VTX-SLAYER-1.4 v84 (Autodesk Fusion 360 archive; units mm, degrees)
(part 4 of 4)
sketch "pressnut3" plane through (0, 0, 7) normal (0, 0, 1) x axis (-1, 0, 0)
  line L1 (-29.8656, 20.8741) -> (-30.0883, 21.2598)
  line L2 (-29.6425, 21.2606) -> (-29.8656, 20.8741)
  line L3 (-29.3373, 20.9286) -> (-29.6331, 21.2615)
  line L4 (-29.1966, 21.352) -> (-29.3373, 20.9286)
  line L5 (-28.8308, 21.0883) -> (-29.1875, 21.3549)
  line L6 (-28.7781, 21.5314) -> (-28.8308, 21.0883)
  line L7 (-28.3667, 21.3467) -> (-28.7698, 21.536)
  line L8 (-28.4044, 21.7913) -> (-28.3667, 21.3467)
  line L9 (-27.9642, 21.6932) -> (-28.3972, 21.7975)
  line L10 (-28.0906, 22.1212) -> (-27.9642, 21.6932)
  line L11 (-27.6397, 22.1137) -> (-28.0848, 22.1287)
  line L12 (-27.8496, 22.5074) -> (-27.6397, 22.1137)
  line L13 (-27.4064, 22.5908) -> (-27.8454, 22.516)
  line L14 (-27.6913, 22.9343) -> (-27.4064, 22.5908)
  line L15 (-27.274, 23.1052) -> (-27.6889, 22.9435)
  line L16 (-27.6222, 23.3843) -> (-27.274, 23.1052)
  line L17 (-27.2478, 23.6357) -> (-27.6217, 23.3938)
  line L18 (-27.6451, 23.8389) -> (-27.2478, 23.6357)
  line L19 (-27.329, 24.1606) -> (-27.6465, 23.8483)
  line L20 (-27.759, 24.2797) -> (-27.329, 24.1606)
  line L21 (-27.5141, 24.6584) -> (-27.7623, 24.2886)
  line L22 (-27.9593, 24.6885) -> (-27.5141, 24.6584)
  line L23 (-27.7957, 25.1088) -> (-27.9644, 24.6966)
  line L24 (-28.2379, 25.0486) -> (-27.7957, 25.1088)
  line L25 (-28.1622, 25.4932) -> (-28.2444, 25.0555)
  line L26 (-28.5832, 25.3453) -> (-28.1622, 25.4932)
  line L27 (-28.5985, 25.796) -> (-28.591, 25.3507)
  line L28 (-28.9811, 25.5664) -> (-28.5985, 25.796)
  line L29 (-29.0869, 26.0048) -> (-28.9899, 25.5702)
  line L30 (-29.4155, 25.7029) -> (-29.0869, 26.0048)
  line L31 (-29.6073, 26.111) -> (-29.4248, 25.7048)
  line L32 (-29.8684, 25.7491) -> (-29.6073, 26.111)
  line L33 (-30.1384, 26.1103) -> (-29.8779, 25.7491)
  line L34 (-30.3213, 25.7032) -> (-30.1384, 26.1103)
  line L35 (-30.6585, 26.0026) -> (-30.3306, 25.7013)
  line L36 (-30.7557, 25.5671) -> (-30.6585, 26.0026)
  line L37 (-31.1463, 25.7925) -> (-30.7645, 25.5634)
  line L38 (-31.1539, 25.3463) -> (-31.1463, 25.7925)
  line L39 (-31.5819, 25.4885) -> (-31.1617, 25.3409)
  line L40 (-31.4994, 25.0499) -> (-31.5819, 25.4885)
  line L41 (-31.9473, 25.103) -> (-31.506, 25.043)
  line L42 (-31.7782, 24.69) -> (-31.9473, 25.103)
  line L43 (-32.2276, 24.6519) -> (-31.7833, 24.682)
  line L44 (-31.9789, 24.2814) -> (-32.2276, 24.6519)
  line L45 (-32.4114, 24.1536) -> (-31.9822, 24.2725)
  line L46 (-32.0932, 23.8407) -> (-32.4114, 24.1536)
  line L47 (-32.4911, 23.6285) -> (-32.0946, 23.8313)
  line L48 (-32.1164, 23.3861) -> (-32.4911, 23.6285)
  line L49 (-32.4634, 23.098) -> (-32.1159, 23.3766)
  line L50 (-32.0477, 22.936) -> (-32.4634, 23.098)
  line L51 (-32.3296, 22.5841) -> (-32.0453, 22.9268)
  line L52 (-31.8897, 22.509) -> (-32.3296, 22.5841)
  line L53 (-32.095, 22.1075) -> (-31.8855, 22.5005)
  line L54 (-31.6491, 22.1226) -> (-32.095, 22.1075)
  line L55 (-31.7694, 21.688) -> (-31.6432, 22.1151)
  line L56 (-31.3355, 21.7925) -> (-31.7694, 21.688)
  line L57 (-31.3659, 21.3425) -> (-31.3283, 21.7863)
  line L58 (-30.962, 21.5323) -> (-31.3659, 21.3425)
  line L59 (-30.9011, 21.0854) -> (-30.9537, 21.5277)
  line L60 (-30.5437, 21.3526) -> (-30.9011, 21.0854)
  line L61 (-30.3941, 20.9271) -> (-30.5346, 21.3497)
  line L62 (-30.0978, 21.2608) -> (-30.3941, 20.9271)
  circle C1 centre (-29.8693, 23.4991) radius 1.55
  arc A1 centre (-29.8693, 23.4991) radius 2.25 clockwise from (-30.0883, 21.2598) to (-30.0978, 21.2608)
  arc A2 centre (-29.8693, 23.4991) radius 2.25 clockwise from (-29.6331, 21.2615) to (-29.6425, 21.2606)
  arc A3 centre (-29.8693, 23.4991) radius 2.25 clockwise from (-29.1875, 21.3549) to (-29.1966, 21.352)
  arc A4 centre (-29.8693, 23.4991) radius 2.25 clockwise from (-28.7698, 21.536) to (-28.7781, 21.5314)
  arc A5 centre (-29.8693, 23.4991) radius 2.25 clockwise from (-28.3972, 21.7975) to (-28.4044, 21.7913)
  arc A6 centre (-29.8693, 23.4991) radius 2.25 clockwise from (-28.0848, 22.1287) to (-28.0906, 22.1212)
  arc A7 centre (-29.8693, 23.4991) radius 2.25 clockwise from (-27.8454, 22.516) to (-27.8496, 22.5074)
  arc A8 centre (-29.8693, 23.4991) radius 2.25 clockwise from (-27.6889, 22.9435) to (-27.6913, 22.9343)
  arc A9 centre (-29.8693, 23.4991) radius 2.25 clockwise from (-27.6217, 23.3938) to (-27.6222, 23.3843)
  arc A10 centre (-29.8693, 23.4991) radius 2.25 clockwise from (-27.6465, 23.8483) to (-27.6451, 23.8389)
  arc A11 centre (-29.8693, 23.4991) radius 2.25 clockwise from (-27.7623, 24.2886) to (-27.759, 24.2797)
  arc A12 centre (-29.8693, 23.4991) radius 2.25 clockwise from (-27.9644, 24.6966) to (-27.9593, 24.6885)
  arc A13 centre (-29.8693, 23.4991) radius 2.25 clockwise from (-28.2444, 25.0555) to (-28.2379, 25.0486)
  arc A14 centre (-29.8693, 23.4991) radius 2.25 clockwise from (-28.591, 25.3507) to (-28.5832, 25.3453)
  arc A15 centre (-29.8693, 23.4991) radius 2.25 clockwise from (-28.9899, 25.5702) to (-28.9811, 25.5664)
  arc A16 centre (-29.8693, 23.4991) radius 2.25 clockwise from (-29.4248, 25.7048) to (-29.4155, 25.7029)
  arc A17 centre (-29.8693, 23.4991) radius 2.25 clockwise from (-29.8779, 25.7491) to (-29.8684, 25.7491)
  arc A18 centre (-29.8693, 23.4991) radius 2.25 clockwise from (-30.3306, 25.7013) to (-30.3213, 25.7032)
  arc A19 centre (-29.8693, 23.4991) radius 2.25 clockwise from (-30.7645, 25.5634) to (-30.7557, 25.5671)
  arc A20 centre (-29.8693, 23.4991) radius 2.25 clockwise from (-31.1617, 25.3409) to (-31.1539, 25.3463)
  arc A21 centre (-29.8693, 23.4991) radius 2.25 clockwise from (-31.506, 25.043) to (-31.4994, 25.0499)
  arc A22 centre (-29.8693, 23.4991) radius 2.25 clockwise from (-31.7833, 24.682) to (-31.7782, 24.69)
  arc A23 centre (-29.8693, 23.4991) radius 2.25 clockwise from (-31.9822, 24.2725) to (-31.9789, 24.2814)
  arc A24 centre (-29.8693, 23.4991) radius 2.25 clockwise from (-32.0946, 23.8313) to (-32.0932, 23.8407)
  arc A25 centre (-29.8693, 23.4991) radius 2.25 clockwise from (-32.1159, 23.3766) to (-32.1164, 23.3861)
  arc A26 centre (-29.8693, 23.4991) radius 2.25 clockwise from (-32.0453, 22.9268) to (-32.0477, 22.936)
  arc A27 centre (-29.8693, 23.4991) radius 2.25 clockwise from (-31.8855, 22.5005) to (-31.8897, 22.509)
  arc A28 centre (-29.8693, 23.4991) radius 2.25 clockwise from (-31.6432, 22.1151) to (-31.6491, 22.1226)
  arc A29 centre (-29.8693, 23.4991) radius 2.25 clockwise from (-31.3283, 21.7863) to (-31.3355, 21.7925)
  arc A30 centre (-29.8693, 23.4991) radius 2.25 clockwise from (-30.9537, 21.5277) to (-30.962, 21.5323)
  arc A31 centre (-29.8693, 23.4991) radius 2.25 clockwise from (-30.5346, 21.3497) to (-30.5437, 21.3526)
  circle C2 centre (-29.8693, 23.4991) radius 3.05
  concentric C1 C2
  dimension "d1051" diameter C2 = 6.1
extrude "Extrude126" add sketch "pressnut3" along normal blind 1.3
copy_paste_bodies "CopyPasteBodies11"
move "Move22"
copy_paste_bodies "CopyPasteBodies12"
move "Move23"
component_from_bodies "Body->Comp25"
component_from_bodies "Body->Comp26"
component_from_bodies "Body->Comp27"
component_from_bodies "Body->Comp28"
component_from_bodies "Body->Comp29"
component_from_bodies "Body->Comp30"
joint "Assemble33" alignAngle 0 alignOffsetX 0 alignOffsetY 0 alignOffsetZ 0
joint "Assemble34" alignAngle 0 alignOffsetX 0 alignOffsetY 0 alignOffsetZ 0
component_insert "Component Insert30"
joint "Assemble35" alignAngle 0 alignOffsetX 0 alignOffsetY 0 alignOffsetZ 0
base_feature "Base Feature1" bodies "arm-fr"
mirror_component "MirrorComponent1"
derived_instance "DerivedInstance1"
mirror_component "MirrorComponent2"
derived_instance "DerivedInstance2"
derived_instance "DerivedInstance3"
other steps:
derived_base_feature "Derived Base Feature1" bodies "arm-fr (1)"
derived_base_feature "Derived Base Feature1" bodies "arm-fr"
base_feature "Base Feature1" bodies "turtleFin"
base_feature "Base Feature1" bodies "vtx-antenna-mount"
derived_base_feature "Derived Base Feature1" bodies "arm-fr (1)", "arm-fr"
base_feature "Base Feature1" bodies "arm-fr"
base_feature "Base Feature1" bodies "arm-rr"
base_feature "Base Feature1" bodies "arm-fl (1)"
base_feature "Base Feature1" bodies "arm-rl"
base_feature "Base Feature1" bodies "m-center"
base_feature "Base Feature1" bodies "m-bottom"
base_feature "Base Feature1" bodies "m-top"
base_feature "Base Feature1" bodies "top (1)"
base_feature "Base Feature1" bodies "cam-mount"
base_feature "Base Feature1" bodies "standoff1 (1)"
base_feature "Base Feature1" bodies "standoff2 (1)"
base_feature "Base Feature1" bodies "standoff1"
base_feature "Base Feature1" bodies "standoff2"
base_feature "Base Feature1" bodies "pressnut1"
base_feature "Base Feature1" bodies "pressnut2"
base_feature "Base Feature1" bodies "pressnut4"
base_feature "Base Feature1" bodies "pressnut5"
base_feature "Base Feature9" bodies "m-bottom", "m-top"
base_feature "Base Feature13" bodies "standoff1", "standoff2", "standoff1 (1)", "standoff2 (1)"
base_feature "Base Feature11" bodies "pressnut", "pressnut2"
base_feature "Base Feature12" bodies "pressnut (1)", "pressnut (1) (1)", "pressnut4", "pressnut5"
joint_origin "JointOrigin14"
joint_origin "JointOrigin15"
joint_origin "JointOrigin16"
joint_origin "JointOrigin17"
joint_origin "JointOrigin18"
joint_origin "JointOrigin19"
joint_origin "JointOrigin20"
joint_origin "JointOrigin21"
joint_origin "JointOrigin22"
joint_origin "JointOrigin23"
joint_origin "JointOrigin24"
joint_origin "JointOrigin25"
joint_origin "JointOrigin26"
joint_origin "JointOrigin27"
joint_origin "JointOrigin28"
joint_origin "JointOrigin29"
joint_origin "JointOrigin30"
create_component "CreateComponent11"
remove_body "RemoveBody11"
create_component "CreateComponent12"
remove_body "RemoveBody12"
create_component "CreateComponent13"
create_component "CreateComponent14"
remove_body "RemoveBody14"
create_component "CreateComponent15"
remove_body "RemoveBody15"
create_component "CreateComponent16"
remove_body "RemoveBody16"
create_component "CreateComponent17"
remove_body "RemoveBody17"
create_component "CreateComponent18"
create_component "CreateComponent19"
remove_body "RemoveBody19"
create_component "CreateComponent21"
create_component "CreateComponent22"
create_component "CreateComponent23"
create_component "CreateComponent24"
create_component "CreateComponent25"
remove_body "RemoveBody25"
create_component "CreateComponent26"
remove_body "RemoveBody26"
create_component "CreateComponent27"
remove_body "RemoveBody27"
create_component "CreateComponent28"
remove_body "RemoveBody28"
remove_body "RemoveBody29"
remove_body "RemoveBody30"
remove_body "RemoveBody31"
remove_body "RemoveBody32"
joint_origin "JointOrigin31"
joint_origin "JointOrigin34"
remove_body "RemoveBody33"
remove_body "RemoveBody34"
create_component "CreateComponent29"
remove_body "RemoveBody35"
create_component "CreateComponent30"
remove_body "RemoveBody36"
joint_origin "JointOrigin1"
joint_origin "JointOrigin2"
joint_origin "JointOrigin1"
create_component "CreateComponent31"
create_component "CreateComponent32"
create_component "CreateComponent33"
create_component "CreateComponent34"
named bodies: "arm-fr", "arm-rr", "arm-rl", "m-bottom", "m-top", "m-center", "cam-mount", "pressnut1", "pressnut", "pressnut2", "pressnut (1)", "pressnut (1) (1)", "pressnut4", "pressnut5", "vtx-antenna-mount", "standoff1", "standoff2", "standoff1 (1)", "standoff2 (1)", "arm-fl", "top", "arm-fl (1)", "top (1)", "turtleFin", "arm-fr (1)"

design "motor"
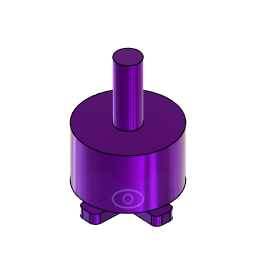
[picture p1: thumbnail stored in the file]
base_feature "Base Feature" bodies "motor (1)"
sketch "Sketch1" plane through (0, 0, 5) normal (0, 0, -1) x axis (1, 0, 0)
  line L1 (57.6027, -10.7672) -> (59.2019, -10.717)
  line L2 (59.1361, -8.618) -> (57.5368, -8.6682)
  line L3 (62.5877, -13.7451) -> (62.6725, -15.3429)
  line L4 (64.7695, -15.2315) -> (64.6847, -13.6338)
  line L5 (67.8976, -10.2308) -> (69.4855, -10.0349)
  line L6 (69.2284, -7.9507) -> (67.6404, -8.1466)
  line L7 (64.8533, -18.5431) -> (63.0539, -18.6377)
  line L8 (65.7504, -12.5921) -> (65.9888, -17.2839)
  line L9 (71.6196, -11.0848) -> (66.8861, -11.3329)
  line L10 (72.661, -8.0261) -> (72.7552, -9.8236)
  line L11 (66.6767, -7.1381) -> (71.3998, -6.8905)
  line L12 (65.1754, -1.2759) -> (65.4155, -6.0006)
  line L13 (62.0887, -0.2348) -> (63.9137, -0.1385)
  line L14 (61.2013, -6.2234) -> (60.9535, -1.4959)
  line L15 (55.3943, -7.7294) -> (60.0658, -7.4845)
  line L16 (54.353, -10.788) -> (54.2588, -8.9905)
  line L17 (60.2857, -11.6788) -> (55.6141, -11.9236)
  line L18 (61.7926, -17.5022) -> (61.5468, -12.8143)
  arc A1 centre (59.169, -9.6675) radius 1.05 clockwise from (59.1361, -8.618) to (59.2019, -10.717)
  arc A2 centre (57.5698, -9.7177) radius 1.05 clockwise from (57.6027, -10.7672) to (57.5368, -8.6682)
  arc A3 centre (63.721, -15.2872) radius 1.05 clockwise from (64.7695, -15.2315) to (62.6725, -15.3429)
  arc A4 centre (63.6362, -13.6895) radius 1.05 clockwise from (62.5877, -13.7451) to (64.6847, -13.6338)
  arc A5 centre (69.357, -8.9928) radius 1.05 clockwise from (69.2284, -7.9507) to (69.4855, -10.0349)
  arc A6 centre (67.769, -9.1887) radius 1.05 clockwise from (67.8976, -10.2308) to (67.6404, -8.1466)
  arc A7 centre (62.9909, -17.4393) radius 1.2 clockwise from (63.0539, -18.6377) to (61.7926, -17.5022)
  arc A8 centre (64.7904, -17.3448) radius 1.2 clockwise from (65.9888, -17.2839) to (64.8533, -18.5431)
  arc A9 centre (66.9489, -12.5312) radius 1.2 clockwise from (65.7504, -12.5921) to (66.8861, -11.3329)
  arc A10 centre (71.5568, -9.8864) radius 1.2 clockwise from (72.7552, -9.8236) to (71.6196, -11.0848)
  arc A11 centre (71.4626, -8.0889) radius 1.2 clockwise from (71.3998, -6.8905) to (72.661, -8.0261)
  arc A12 centre (66.6139, -5.9397) radius 1.2 clockwise from (66.6767, -7.1381) to (65.4155, -6.0006)
  arc A13 centre (63.9769, -1.3368) radius 1.2 clockwise from (63.9137, -0.1385) to (65.1754, -1.2759)
  arc A14 centre (62.1519, -1.4331) radius 1.2 clockwise from (60.9535, -1.4959) to (62.0887, -0.2348)
  arc A15 centre (60.003, -6.2862) radius 1.2 clockwise from (61.2013, -6.2234) to (60.0658, -7.4845)
  arc A16 centre (55.4571, -8.9277) radius 1.2 clockwise from (54.2588, -8.9905) to (55.3943, -7.7294)
  arc A17 centre (55.5513, -10.7252) radius 1.2 clockwise from (55.6141, -11.9236) to (54.353, -10.788)
  arc A18 centre (60.3485, -12.8771) radius 1.2 clockwise from (60.2857, -11.6788) to (61.5468, -12.8143)
  circle C1 centre (63.469, -9.3895) radius 2.5
named bodies: "motor (1)"

design "M2 screw size FLAT WASHER"
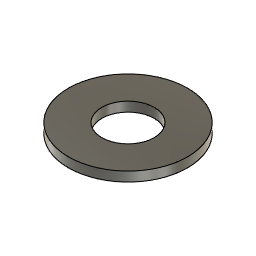
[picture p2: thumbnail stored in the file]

design "runcam_phoenix_2"
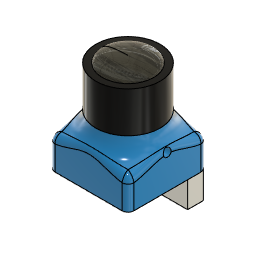
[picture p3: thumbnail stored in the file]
sketch "Skizze1" plane through (0, 0, 0) normal (0, 0, 1) x axis (1, 0, 0)
  line L1 (20, 0) -> (0, 0)
  line L2 (20, 20) -> (20, 0)
  line L3 (0, 20) -> (20, 20)
  line L4 (0, 0) -> (0, 20)
  point P1 (0, 0)
  point P2 (0, 0)
  point P3 (20, 0)
  point P5 (0, 20)
  horizontal L1
  vertical L2
  horizontal L3
  vertical L4
  coincident P1 P2
  dimension "d1" distance P2 P3 = 20
  dimension "d2" distance P2 P5 = 20
extrude "Extrusion1" new body sketch "Skizze1" along normal blind 8
sketch "Skizze2" plane through (0, 0, 8) normal (0, 0, 1) x axis (-1, 0, 0)
  line L1 (0, 0) -> (0, -20)
  line L2 (-20, 0) -> (0, 0)
  line L3 (-20, -20) -> (-20, 0)
  line L4 (0, -20) -> (-20, -20)
  circle C1 centre (-10, -10) radius 8.15
  dimension "d5" diameter C1 = 16.3
extrude "Extrusion2" add sketch "Skizze2" profile of C1 along normal blind 15.3
fillet "Abrundung1" radius 1.5
fillet "Abrundung2" radius 5
fillet "Abrundung3" radius 2
sphere_primitive "Grundkörper Kugel" Diameter 13
scale "Maßstab" ScaleZ 0.2475
split "Teilen1"
work_plane "Arbeitsebene" AlongDistance -13
split "Teilen2"
sketch "Skizze4" plane through (20, 0, 0) normal (1, 0, 0) x axis (0, 1, 0)
  curve K1 (18.5, 6.1577) -> (1.5, 6.1577)
  line L1 (1.5, 0) -> (1.5, 6.1577)
  line L2 (18.5, 0) -> (1.5, 0)
  line L3 (18.5, 6.1577) -> (18.5, 0)
  circle C1 centre (10, 8.5) radius 0.975
  point P6 (10, 8.5)
  dimension "d19" diameter C1 = 1.95
  dimension "d20" distance L2 P6 = 8.5
extrude "Extrusion3" cut sketch "Skizze4" profile of C1 against normal blind 4
sketch "Skizze5" plane through (0, 0, 0) normal (-1, 0, 0) x axis (0, -1, 0)
  curve K1 (-1.5, 6.1577) -> (-18.5, 6.1577)
  line L1 (-18.5, 0) -> (-18.5, 6.1577)
  line L2 (-1.5, 0) -> (-18.5, 0)
  line L3 (-1.5, 6.1577) -> (-1.5, 0)
  curve K2 (-10.9281, 8.2013) -> (-9.0719, 8.2013)
  arc A1 centre (-10, 8.5) radius 0.975 clockwise from (-9.0719, 8.2013) to (-10.9281, 8.2013)
extrude "Extrusion4" cut sketch "Skizze5" profile of A1 against normal blind 4
sketch "Skizze7" plane through (0, 0, 0) normal (0, 0, -1) x axis (1, 0, 0)
  line L1 (20, -1.5) -> (20, -18.5)
  line L2 (1.5, 0) -> (18.5, 0)
  line L3 (18.5, -20) -> (1.5, -20)
  line L4 (9.5607, -19.5607) -> (19.5607, -19.5607)
  line L5 (9.5607, -15.5607) -> (9.5607, -19.5607)
  line L6 (19.5607, -15.5607) -> (9.5607, -15.5607)
  line L7 (19.5607, -19.5607) -> (19.5607, -15.5607)
  line L8 (0, -18.5) -> (0, -1.5)
  arc A1 centre (18.5, -18.5) radius 1.5 clockwise from (20, -18.5) to (18.5, -20)
  arc A2 centre (18.5, -1.5) radius 1.5 clockwise from (18.5, 0) to (20, -1.5)
  arc A3 centre (1.5, -1.5) radius 1.5 clockwise from (0, -1.5) to (1.5, 0)
  arc A4 centre (1.5, -18.5) radius 1.5 clockwise from (1.5, -20) to (0, -18.5)
  point P14 (19.5607, -19.5607)
  point P15 (9.5607, -19.5607)
  point P17 (19.5607, -15.5607)
  horizontal L4
  vertical L5
  horizontal L6
  vertical L7
  midpoint A1 P14
  dimension "d25" distance P14 P15 = 10
  dimension "d26" distance P14 P17 = 4
extrude "Extrusion5" new body sketch "Skizze7" profile of L4 L5 L6 L7 along normal blind 7

design "M2 x 0.4mm Thread 5mm LONG SOCKET HEAD CAP SCREW"
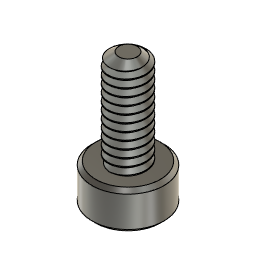
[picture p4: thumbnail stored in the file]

design "M3 x 0.5mm Thread 8mm LONG SOCKET HEAD CAP SCREW"
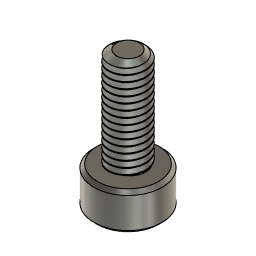
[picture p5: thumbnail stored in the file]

design "nut"
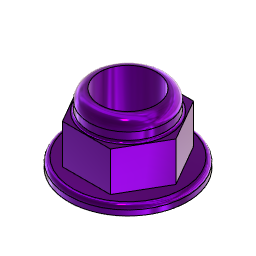
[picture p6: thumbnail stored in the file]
base_feature "Base Feature" bodies "nut (1)"
sketch "Sketch1" plane through (0, 0, 0) normal (1, 0, 0) x axis (0, 1, 0)
  line L1 (3.5, 35.5147) -> (15.2246, 35.5147)
  line L2 (3.5, 31.9) -> (3.5, 35.5147)
  line L3 (15.2246, 31.9) -> (3.5, 31.9)
  line L4 (15.2246, 35.5147) -> (15.2246, 31.9)
  line L5 (6.6576, 31.9) -> (12.1213, 31.9)
  line L6 (15.1073, 25.3) -> (3.6716, 25.3)
  line L7 (21.1207, 2.6841) -> (-6.8795, 2.6841)
  line L8 (21.1207, 25.3) -> (21.1207, 2.6841)
  line L9 (-6.8795, 25.3) -> (21.1207, 25.3)
  line L10 (-6.8795, 2.6841) -> (-6.8795, 25.3)
  point P4 (3.5, 31.9)
  point P9 (15.1073, 25.3)
  horizontal L1
  vertical L2
  horizontal L3
  vertical L4
  coincident P4 L5
  horizontal L7
  vertical L8
  horizontal L9
  vertical L10
  coincident P9 L9
extrude "Extrude3" cut sketch "Sketch1" along normal blind 90
extrude "Extrude4" cut of existing geometry blind -11
named bodies: "nut (1)"

design "M2 x 0.4mm Thread HEX NUT"
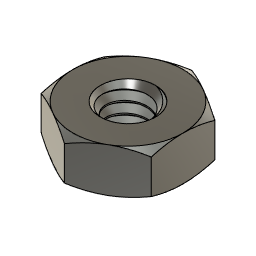
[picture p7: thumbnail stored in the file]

design "M3 x 0.5mm Thread 16mm LONG SOCKET HEAD CAP SCREW"
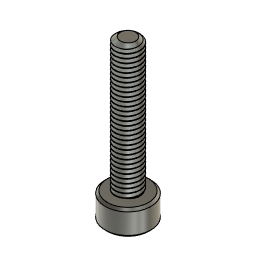
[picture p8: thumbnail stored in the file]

design "prop"
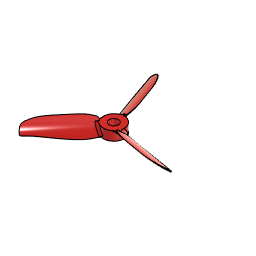
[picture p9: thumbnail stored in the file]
base_feature "Base Feature" bodies "prop (1)"
named bodies: "prop (1)"

design "M2 x 0.4mm Thread 20mm LONG SOCKET HEAD CAP SCREW"
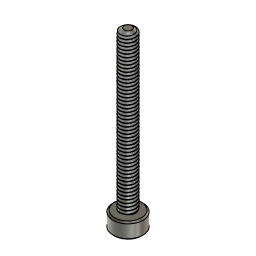
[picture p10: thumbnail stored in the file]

design "vtx-slayer-caddx-antenna-mount"
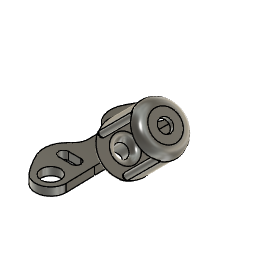
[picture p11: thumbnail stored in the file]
sketch "Sketch1" plane through (0, 0, 0) normal (0, 0, 1) x axis (1, 0, 0)
  curve K1 (-38.8418, 18.921) -> (-40.1385, 19.823)
  curve K2 (-38.8418, -19.2056) -> (-40.1385, -20.1076)
  line L1 (3.6352, 20.2947) -> (5.3093, 18.4714)
  line L2 (-9.7947, 19.0197) -> (-9.7947, -14.7467)
  curve K3 (5.3089, 7.3613) -> (5.6973, 10.2747)
  line L3 (-2.8247, -10.6423) -> (1.1551, -10.6423)
  line L4 (-24.7842, -3.9569) -> (-28.5094, -7.7125)
  line L5 (1.1551, 7.3577) -> (-2.8247, 7.3577)
  curve K4 (-38.6331, 18.7841) -> (-38.8418, 18.921)
  curve K5 (-6.4509, 19.823) -> (-7.7476, 18.921)
  curve K6 (-7.9563, -19.0687) -> (-7.7476, -19.2056)
  curve K7 (-23.2947, -15.121) -> (-30.8503, -15.7545)
  curve K8 (-6.4509, -20.1076) -> (-3.6425, -21.7969)
  curve K9 (-7.9563, 18.7841) -> (-7.7476, 18.921)
  line L6 (1.1551, -10.6423) -> (-2.8247, -10.6423)
  curve K10 (-7.7476, -19.2056) -> (-6.4509, -20.1076)
  line L7 (5.3093, 18.4714) -> (3.6352, 20.2947)
  curve K11 (3.6352, 20.2947) -> (-3.6425, 21.5123)
  curve K12 (5.3089, -7.6459) -> (5.6973, -10.5593)
  curve K13 (-30.8503, -15.7545) -> (-30.9348, -15.7714)
  line L8 (1.1551, 10.3577) -> (-2.8247, 10.3577)
  line L9 (-27.0894, -11.121) -> (-19.5779, -11.121)
  curve K14 (-6.4509, 19.823) -> (-3.6425, 21.5123)
  line L10 (-41.2466, -2.9822) -> (-37.7303, -6.47)
  line L11 (-50.2246, -20.5793) -> (-56.7662, -13.4545)
  line L12 (-2.9703, -1.0887) -> (-2.9703, 0.8041)
  line L13 (-32.83, -6.3884) -> (-29.4286, -2.9592)
  line L14 (-2.8247, 10.3577) -> (1.1551, 10.3577)
  curve K15 (-40.1385, -20.1076) -> (-42.9469, -21.7969)
  line L15 (-17.2468, -2.9822) -> (-13.8129, -6.3883)
  curve K16 (5.6973, 10.2747) -> (5.3093, 18.4714)
  curve K17 (-3.6425, -21.7969) -> (3.6352, -20.5793)
  line L16 (-19.5779, 10.8364) -> (-27.0894, 10.8364)
  line L17 (-38.5595, -11.2815) -> (-44.8889, -5.0034)
  line L18 (1.1551, -7.6423) -> (-2.8247, -7.6423)
  curve K18 (5.3089, 7.3613) -> (5.6973, 10.2747)
  curve K19 (-30.8503, 15.4699) -> (-30.9348, 15.4868)
  line L19 (-2.8247, 7.3577) -> (1.1551, 7.3577)
  curve K20 (-30.9348, -15.7714) -> (-38.6331, -19.0687)
  curve K21 (-23.2947, 14.8364) -> (-30.8503, 15.4699)
  curve K22 (5.6973, 10.2747) -> (5.3093, 18.4714)
  line L20 (-37.7303, 6.1854) -> (-41.2466, 2.6976)
  curve K23 (5.3093, -18.756) -> (5.6973, -10.5593)
  curve K24 (-30.9348, 15.4868) -> (-38.6331, 18.7841)
  line L21 (5.3061, -7.62) -> (5.3061, 7.3354)
  curve K25 (-42.9469, 21.5123) -> (-50.2246, 20.2947)
  curve K26 (5.3093, -18.756) -> (5.6973, -10.5593)
  line L22 (-18.1694, -7.701) -> (-21.9558, -3.9454)
  line L23 (-4.4558, 4.3605) -> (-7.2583, 7.1299)
  curve K27 (-38.6331, -19.0687) -> (-38.8418, -19.2056)
  line L24 (-7.2583, -7.4145) -> (-4.4558, -4.6451)
  line L25 (3.6352, -20.5793) -> (5.3093, -18.756)
  curve K28 (-15.6546, 15.4868) -> (-7.9563, 18.7841)
  curve K29 (-23.2947, 14.8364) -> (-15.7391, 15.4699)
  curve K30 (-42.9469, -21.7969) -> (-50.2246, -20.5793)
  line L26 (12.836, -0.1423) -> (-11.2342, -0.1423)
  line L27 (-2.8247, -7.6423) -> (1.1551, -7.6423)
  curve K31 (-15.6546, -15.7714) -> (-7.9563, -19.0687)
  line L28 (5.3061, 7.3354) -> (5.3089, 7.3613)
  curve K32 (-15.7391, -15.7545) -> (-15.6546, -15.7714)
  line L29 (5.3061, 7.3354) -> (5.5261, 16.3821)
  line L30 (5.3089, -7.6459) -> (5.3061, -7.62)
  curve K33 (-15.7391, 15.4699) -> (-15.6546, 15.4868)
  curve K34 (5.3061, -7.62) -> (2.7884, -4.3325)
  curve K35 (-23.2947, -15.121) -> (-15.7391, -15.7545)
  curve K36 (-42.9469, -21.7969) -> (-40.1385, -20.1076)
  line L31 (5.3061, -7.62) -> (5.5261, -16.6667)
  curve K37 (5.3061, 7.3354) -> (2.7884, 4.0479)
  curve K38 (3.6352, -20.5793) -> (-3.6425, -21.7969)
  line L32 (-21.9558, 3.6608) -> (-18.1694, 7.4164)
  curve K39 (-7.7476, -19.2056) -> (-6.4509, -20.1076)
  curve K40 (-40.1385, 19.823) -> (-42.9469, 21.5123)
  curve K41 (-7.7476, 18.921) -> (-6.4509, 19.823)
  line L33 (-28.5094, 7.4279) -> (-24.7842, 3.6723)
  line L34 (-56.7662, 13.1699) -> (-50.2246, 20.2947)
  line L35 (5.3093, -18.756) -> (3.6352, -20.5793)
  line L36 (-13.8129, 6.1037) -> (-17.2468, 2.6976)
  line L37 (-29.4286, 2.6746) -> (-32.83, 6.1038)
  line L38 (-44.8889, 4.7188) -> (-38.5595, 10.9969)
  arc A1 centre (-61.0129, -0.1423) radius 10 clockwise from (-56.0463, 8.5372) to (-56.0463, -8.8218)
  arc A2 centre (1.1551, 8.8577) radius 1.5 clockwise from (1.1551, 10.3577) to (1.1551, 7.3577)
  arc A3 centre (-2.8247, 8.8577) radius 1.5 clockwise from (-2.8247, 7.3577) to (-2.8247, 10.3577)
  circle C1 centre (-47.2947, -16.6423) radius 1.55
  arc A4 centre (1.1551, -9.1423) radius 1.5 clockwise from (1.1551, -7.6423) to (1.1551, -10.6423)
  circle C2 centre (-47.2947, 16.3577) radius 1.55
  arc A5 centre (-35.6177, 4.0554) radius 3 clockwise from (-37.7303, 6.1854) to (-34.5026, 6.8405)
  arc A6 centre (-33.2947, 9.8577) radius 3.25 clockwise from (-33.886, 6.6619) to (-34.5026, 6.8405)
  arc A7 centre (-39.9679, 12.4169) radius 2 clockwise from (-39.3409, 14.3161) to (-38.5595, 10.9969)
  arc A8 centre (-34.2499, 4.6953) radius 2 clockwise from (-33.886, 6.6619) to (-32.83, 6.1038)
  arc A9 centre (-61.0129, -0.1423) radius 14 clockwise from (-49.4166, 7.7015) to (-48.1368, 5.3536)
  circle C3 centre (0.7053, 16.3577) radius 1.55
  arc A10 centre (-27.0894, 8.8364) radius 2 clockwise from (-28.5094, 7.4279) to (-27.0894, 10.8364)
  arc A11 centre (-47.76, -9.1067) radius 2 clockwise from (-47.6367, -11.1028) to (-49.4166, -7.9861)
  arc A12 centre (-47.2947, 16.3577) radius 5.55 clockwise from (-42.7422, 13.1832) to (-47.6367, 10.8182)
  circle C4 centre (0.7053, -16.6423) radius 3.025
  arc A13 centre (-34.2499, -4.9799) radius 2 clockwise from (-32.83, -6.3884) to (-33.886, -6.9465)
  arc A14 centre (1.1551, -9.1423) radius 1.5 clockwise from (1.1551, -7.6423) to (1.1551, -10.6423)
  arc A15 centre (4.4291, -0.1423) radius 4.5 clockwise from (2.7884, -4.3325) to (2.7884, 4.0479)
  arc A16 centre (-23.3642, -5.3653) radius 2 clockwise from (-24.7842, -3.9569) to (-21.9558, -3.9454)
  arc A17 centre (-2.8247, -9.1423) radius 1.5 clockwise from (-2.8247, -10.6423) to (-2.8247, -7.6423)
  arc A18 centre (-14.4299, -0.1423) radius 4 clockwise from (-17.2468, -2.9822) to (-17.2468, 2.6976)
  circle C5 centre (0.7053, -16.6423) radius 4.8209
  arc A19 centre (-23.3642, 5.0807) radius 2 clockwise from (-21.9558, 3.6608) to (-24.7842, 3.6723)
  arc A20 centre (-9.367, 4.9961) radius 3 clockwise from (-11.2523, 7.3296) to (-7.2583, 7.1299)
  arc A21 centre (-7.9703, -1.0887) radius 5 clockwise from (-2.9703, -1.0887) to (-4.4558, -4.6451)
  arc A22 centre (-39.9679, -12.7015) radius 2 clockwise from (-38.5595, -11.2815) to (-39.3409, -14.6007)
  arc A23 centre (1.1551, 8.8577) radius 1.5 clockwise from (1.1551, 10.3577) to (1.1551, 7.3577)
  arc A24 centre (-12.4044, 4.6837) radius 2 clockwise from (-13.8129, 6.1037) to (-12.7436, 6.6548)
  arc A25 centre (-35.6177, -4.34) radius 3 clockwise from (-34.5026, -7.1251) to (-37.7303, -6.47)
  arc A26 centre (-40.2814, 11.4673) radius 3 clockwise from (-42.7422, 13.1832) to (-39.3409, 14.3161)
  arc A27 centre (-46.2973, 6.1387) radius 2 clockwise from (-44.8889, 4.7188) to (-48.1368, 5.3536)
  circle C6 centre (-13.2947, -10.1423) radius 1.05
  arc A28 centre (-46.2973, -6.4233) radius 2 clockwise from (-48.1368, -5.6382) to (-44.8889, -5.0034)
  arc A29 centre (-32.2685, -0.1423) radius 4 clockwise from (-29.4286, 2.6746) to (-29.4286, -2.9592)
  arc A30 centre (-47.76, 8.8221) radius 2 clockwise from (-49.4166, 7.7015) to (-47.6367, 10.8182)
  arc A31 centre (21.8344, -0.1422) radius 31.6291 clockwise from (-3.1211, -19.5748) to (-3.1115, 19.3027)
  arc A32 centre (-13.2947, 9.8577) radius 3.25 clockwise from (-11.2523, 7.3296) to (-12.7436, 6.6548)
  arc A33 centre (-27.0894, -9.121) radius 2 clockwise from (-27.0894, -11.121) to (-28.5094, -7.7125)
  circle C7 centre (0.7053, -16.6423) radius 1.55
  arc A34 centre (-9.367, -5.2807) radius 3 clockwise from (-7.2583, -7.4145) to (-11.2523, -7.6142)
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  point P8 (5.3061, 7.3354)
  point P24 (5.3061, 7.3354)
  point P18 (5.3061, 7.3354)
  point P20 (5.5261, 16.3821)
  point P34 (5.5261, -16.6667)
  point P27 (5.3061, -7.62)
  point P30 (-3.1211, -19.5748)
  perpendicular L2 L26
  coincident P8 P24
  coincident P8 P18
  symmetric P20 P34 L26
  symmetric P18 P27 L26
  tangent L2 A31
  coincident P30 C5
  dimension "d1057" diameter = 6.05
extrude "Extrude1" new body sketch "Sketch1" along normal blind 2.5
sketch "Sketch2" plane through (0, 0, 2.5) normal (0, 0, 1) x axis (-1, 0, 0)
  line L1 (-1.1551, 7.6423) -> (2.8247, 7.6423)
  line L2 (2.8247, 10.6423) -> (-1.1551, 10.6423)
  line L3 (2.8247, -7.3577) -> (-1.1551, -7.3577)
  line L4 (-1.1551, -10.3577) -> (2.8247, -10.3577)
  curve K1 (-5.3061, -7.3354) -> (-2.7884, -4.0479)
  line L5 (-5.5261, -16.3821) -> (-5.3061, -7.3354)
  line L6 (4.4558, -4.3605) -> (7.2583, -7.1299)
  line L7 (2.9703, 1.0887) -> (2.9703, -0.8041)
  line L8 (7.2583, 7.4145) -> (4.4558, 4.6451)
  line L9 (-5.3061, 7.62) -> (-5.5261, 16.6667)
  curve K2 (-2.7884, 4.3325) -> (-5.3061, 7.62)
  line L10 (-19.5, -13) -> (-10.5, -13)
  line L11 (-19.5, 15) -> (-19.5, -13)
  line L12 (-10.5, 15) -> (-19.5, 15)
  line L13 (-10.5, -13) -> (-10.5, 15)
  arc A1 centre (2.8247, 9.1423) radius 1.5 clockwise from (2.8247, 10.6423) to (2.8247, 7.6423)
  arc A2 centre (-1.1551, 9.1423) radius 1.5 clockwise from (-1.1551, 7.6423) to (-1.1551, 10.6423)
  circle C1 centre (-0.7053, 16.6423) radius 3.025
  arc A3 centre (-1.1551, -8.8577) radius 1.5 clockwise from (-1.1551, -10.3577) to (-1.1551, -7.3577)
  arc A4 centre (2.8247, -8.8577) radius 1.5 clockwise from (2.8247, -7.3577) to (2.8247, -10.3577)
  circle C2 centre (-0.7053, -16.3577) radius 3.025
  arc A5 centre (-4.4291, 0.1423) radius 4.5 clockwise from (-2.7884, 4.3325) to (-2.7884, -4.0479)
  arc A6 centre (-0.7053, -16.3577) radius 4.8209 clockwise from (3.1115, -19.3027) to (-5.5261, -16.3821)
  arc A7 centre (-21.8344, 0.1422) radius 31.6291 clockwise from (8.7469, -7.9313) to (3.1115, -19.3027)
  arc A8 centre (9.367, -4.9961) radius 3 clockwise from (8.7469, -7.9313) to (7.2583, -7.1299)
  arc A9 centre (7.9703, -0.8041) radius 5 clockwise from (4.4558, -4.3605) to (2.9703, -0.8041)
  arc A10 centre (7.9703, 1.0887) radius 5 clockwise from (2.9703, 1.0887) to (4.4558, 4.6451)
  arc A11 centre (9.367, 5.2807) radius 3 clockwise from (7.2583, 7.4145) to (8.7469, 8.2159)
  arc A12 centre (-21.8344, 0.1422) radius 31.6291 clockwise from (3.1211, 19.5748) to (8.7469, 8.2159)
  arc A13 centre (-0.7053, 16.6423) radius 4.8209 clockwise from (-5.5261, 16.6667) to (3.1211, 19.5748)
  circle C3 centre (-15, 0) radius 2.1
  circle C4 centre (-15, 0) radius 4
  circle C5 centre (-15, 0) radius 5.55
  circle C6 centre (-15, 0) radius 7.55
  point P40 (-15, 0)
  point P41 (-15, 0)
  concentric C3 C4
  concentric C3 C5
  concentric C5 C6
  horizontal L10
  vertical L11
  horizontal L12
  vertical L13
  dimension "d4" diameter C3 = 4.2
  dimension "d5" diameter C5 = 11.1
  dimension "d6" diameter C6 = 15.1 (= "11.1 mm + 4 mm")
  dimension "d31" distance P40 L13 = 4.5
  dimension "d32" distance P41 L11 = 4.5 (= "d31")
extrude "Extrude2" new body sketch "Sketch2" profile of C3 C4 against normal blind 18
extrude "Extrude3" add sketch "Sketch2" profile of C3 C4 C5 C6 against normal blind 2
extrude "Extrude4" add sketch "Sketch2" profile of C5 C6 along normal blind 15.3
sketch "Sketch3" plane through (0, 0, 17.8) normal (0, 0, 1) x axis (-1, 0, 0)
  circle C1 centre (-15, 0) radius 5.55
  circle C2 centre (-15, 0) radius 7.55
  circle C3 centre (-15, 0) radius 5.55
extrude "Extrude5" add sketch "Sketch3" along normal blind 2.5
extrude "Extrude6" cut sketch "Sketch2" profile of C3 C4 C5 C6 L10 L11 L12 L13 along normal blind 15.3
extrude "Extrude7" cut sketch "Sketch2" profile of C3 along normal blind 19
fillet "Fillet1" radius 2
fillet "Fillet2" radius 3
move "Move1"
move "Move2"
sketch "Sketch4" plane through (0, 0, 2.5) normal (0, 0, 1) x axis (-1, 0, 0)
  line L1 (-1.1551, 7.6423) -> (2.8247, 7.6423)
  line L2 (2.8247, 10.6423) -> (-1.1551, 10.6423)
  line L3 (2.8247, -7.3577) -> (-1.1551, -7.3577)
  line L4 (-1.1551, -10.3577) -> (2.8247, -10.3577)
  curve K1 (-5.3061, -7.3354) -> (-2.7884, -4.0479)
  line L5 (-5.5261, -16.3821) -> (-5.3061, -7.3354)
  line L6 (4.4558, -4.3605) -> (7.2583, -7.1299)
  line L7 (2.9703, 1.0887) -> (2.9703, -0.8041)
  line L8 (7.2583, 7.4145) -> (4.4558, 4.6451)
  line L9 (-5.3061, 7.62) -> (-5.5261, 16.6667)
  curve K2 (-2.7884, 4.3325) -> (-5.3061, 7.62)
  line L10 (0.8348, 7.62) -> (-5.3061, 7.62)
  line L11 (0.8348, -7.3577) -> (0.8348, 7.62)
  line L12 (-5.3061, -7.3577) -> (0.8348, -7.3577)
  line L13 (-5.3061, 7.62) -> (-5.3061, -7.3577)
  arc A1 centre (2.8247, 9.1423) radius 1.5 clockwise from (2.8247, 10.6423) to (2.8247, 7.6423)
  arc A2 centre (-1.1551, 9.1423) radius 1.5 clockwise from (-1.1551, 7.6423) to (-1.1551, 10.6423)
  circle C1 centre (-0.7053, 16.6423) radius 3.025
  arc A3 centre (-1.1551, -8.8577) radius 1.5 clockwise from (-1.1551, -10.3577) to (-1.1551, -7.3577)
  arc A4 centre (2.8247, -8.8577) radius 1.5 clockwise from (2.8247, -7.3577) to (2.8247, -10.3577)
  circle C2 centre (-0.7053, -16.3577) radius 3.025
  arc A5 centre (-4.4291, 0.1423) radius 4.5 clockwise from (-2.7884, 4.3325) to (-2.7884, -4.0479)
  arc A6 centre (-0.7053, -16.3577) radius 4.8209 clockwise from (3.1115, -19.3027) to (-5.5261, -16.3821)
  arc A7 centre (-21.8344, 0.1422) radius 31.6291 clockwise from (8.7469, -7.9313) to (3.1115, -19.3027)
  arc A8 centre (9.367, -4.9961) radius 3 clockwise from (8.7469, -7.9313) to (7.2583, -7.1299)
  arc A9 centre (7.9703, -0.8041) radius 5 clockwise from (4.4558, -4.3605) to (2.9703, -0.8041)
  arc A10 centre (7.9703, 1.0887) radius 5 clockwise from (2.9703, 1.0887) to (4.4558, 4.6451)
  arc A11 centre (9.367, 5.2807) radius 3 clockwise from (7.2583, 7.4145) to (8.7469, 8.2159)
  arc A12 centre (-21.8344, 0.1422) radius 31.6291 clockwise from (3.1211, 19.5748) to (8.7469, 8.2159)
  arc A13 centre (-0.7053, 16.6423) radius 4.8209 clockwise from (-5.5261, 16.6667) to (3.1211, 19.5748)
  point P40 (0.8348, -7.3577)
  point P37 (-5.3061, 7.62)
  point P38 (-5.3061, 7.62)
  horizontal L10
  vertical L11
  horizontal L12
  vertical L13
  midpoint L3 P40
  coincident P37 P38
combine "Combine1"
extrude "Extrude8" add sketch "Sketch4" profile of L3 A5 K1 K2 L10 L11 L12 L13 against normal blind 2.5
sketch "Sketch5" plane through (0, 0, 0) normal (0, 0, -1) x axis (1, 0, 0)
  line L1 (-2.8247, -10.3577) -> (1.1551, -10.3577)
  line L2 (1.1551, -7.3577) -> (-2.8247, -7.3577)
  line L3 (1.1551, 10.6423) -> (-2.8247, 10.6423)
  line L4 (-2.8247, 7.6423) -> (1.1551, 7.6423)
  curve K1 (5.1293, 3.8257) -> (5.3061, 3.7724)
  line L5 (5.3061, 7.62) -> (5.3061, 3.7724)
  line L6 (5.5261, 16.6667) -> (5.3061, 7.62)
  line L7 (-4.4558, 4.6451) -> (-7.2583, 7.4145)
  line L8 (-2.9703, -0.8041) -> (-2.9703, 1.0887)
  line L9 (-7.2583, -7.1299) -> (-4.4558, -4.3605)
  line L10 (5.3061, -7.3354) -> (5.5261, -16.3821)
  line L11 (5.3061, -3.4724) -> (5.3061, -7.3354)
  curve K2 (5.3061, -3.4724) -> (5.1293, -3.5257)
  line L12 (14.9567, 9) -> (-10, 9)
  line L13 (14.9567, -11.2013) -> (14.9567, 9)
  line L14 (-10, -11.2013) -> (14.9567, -11.2013)
  line L15 (-10, 9) -> (-10, -11.2013)
  arc A1 centre (1.1551, -8.8577) radius 1.5 clockwise from (1.1551, -7.3577) to (1.1551, -10.3577)
  arc A2 centre (-2.8247, -8.8577) radius 1.5 clockwise from (-2.8247, -10.3577) to (-2.8247, -7.3577)
  arc A3 centre (-2.8247, 9.1423) radius 1.5 clockwise from (-2.8247, 7.6423) to (-2.8247, 10.6423)
  arc A4 centre (1.1551, 9.1423) radius 1.5 clockwise from (1.1551, 10.6423) to (1.1551, 7.6423)
  circle C1 centre (0.7053, 16.6423) radius 3.025
  closed curve K3 centre (2.8981, 0.15)
  arc A5 centre (0.7053, 16.6423) radius 4.8209 clockwise from (-3.1211, 19.5748) to (5.5261, 16.6667)
  arc A6 centre (21.8344, 0.1422) radius 31.6291 clockwise from (-8.7469, 8.2159) to (-3.1211, 19.5748)
  arc A7 centre (-9.367, 5.2807) radius 3 clockwise from (-8.7469, 8.2159) to (-7.2583, 7.4145)
  arc A8 centre (-7.9703, 1.0887) radius 5 clockwise from (-4.4558, 4.6451) to (-2.9703, 1.0887)
  arc A9 centre (-7.9703, -0.8041) radius 5 clockwise from (-2.9703, -0.8041) to (-4.4558, -4.3605)
  arc A10 centre (-9.367, -4.9961) radius 3 clockwise from (-7.2583, -7.1299) to (-8.7469, -7.9313)
  arc A11 centre (21.8344, 0.1422) radius 31.6291 clockwise from (-3.1115, -19.3027) to (-8.7469, -7.9313)
  arc A12 centre (0.7053, -16.3577) radius 4.8209 clockwise from (5.5261, -16.3821) to (-3.1115, -19.3027)
  circle C2 centre (0.7053, -16.3577) radius 3.025
  horizontal L12
  vertical L13
  horizontal L14
  vertical L15
extrude "Extrude9" cut sketch "Sketch5" profile of A1 L1 A2 L2 A3 A4 L4 K3 K1 L5 L6 A6 A7 L7 A8 L8 A9 L9 A10 A11 L10 L11 K2 L12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 along normal blind 13
sketch "Sketch6" plane through (18.6867, 0, 18.6867) normal (0.7071, 0, 0.7071) x axis (0, 1, 0)
  circle C1 centre (-0.15, -2.0493) radius 2.1
  circle C2 centre (-0.15, -2.0493) radius 4.55
extrude "Extrude10" cut sketch "Sketch6" profile of C1 against normal blind 50
fillet "Fillet3" radius 7
fillet "Fillet4" radius 1
chamfer "Chamfer1" distance 3.5 distance 1

design "M2 x 0.4mm Thread 6mm LONG SOCKET HEAD CAP SCREW"
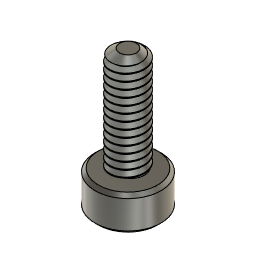
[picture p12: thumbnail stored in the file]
